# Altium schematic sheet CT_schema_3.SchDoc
size 321 x 189 mm
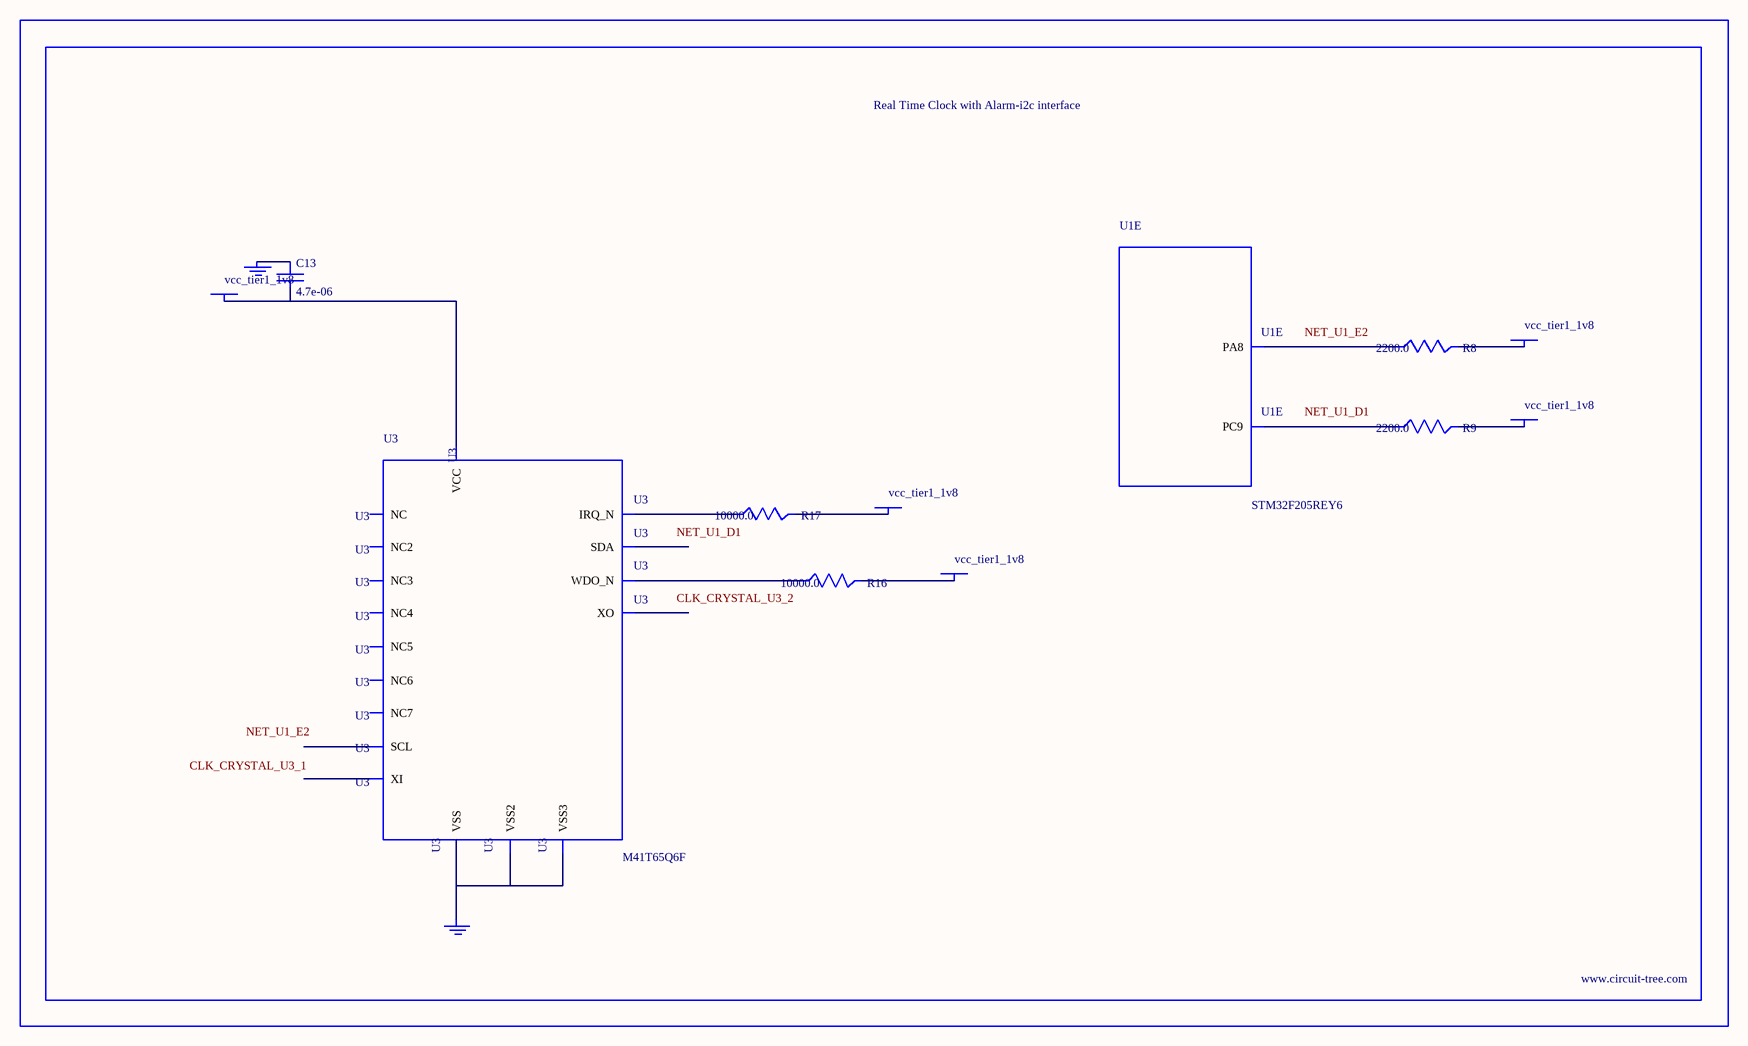
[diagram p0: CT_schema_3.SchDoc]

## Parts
BORDER2  (no value)
C13  4.7e-06  [C0805]
GND_INSTANCE_2_0  (no value)
GND_INSTANCE_2_1  (no value)
POWER_INSTANCE_2_0  vcc_tier1_1v8
POWER_INSTANCE_2_1  vcc_tier1_1v8
POWER_INSTANCE_2_2  vcc_tier1_1v8
POWER_INSTANCE_2_3  vcc_tier1_1v8
POWER_INSTANCE_2_4  vcc_tier1_1v8
R8  2200.0  [R0603]
R9  2200.0  [R0603]
R16  10000.0  [R0603]
R17  10000.0  [R0603]
U1  STM32F205REY6  [WLCSP66]  (part E of 7)
U3  M41T65Q6F  [M41T65_QFN-16]

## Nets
NetC13_1: C13.1 GND_INSTANCE_2_0.0(GND)
NetC13_2: C13.2 POWER_INSTANCE_2_2.0(PWR) U3.14(VCC)
NetGND_INSTANCE_2_1_0: GND_INSTANCE_2_1.0(GND) U3.3(VSS) U3.5(VSS2) U3.17(VSS3)
NetPOWER_INSTANCE_2_0_0: POWER_INSTANCE_2_0.0(PWR) R16.2
NetPOWER_INSTANCE_2_1_0: POWER_INSTANCE_2_1.0(PWR) R17.2
NetPOWER_INSTANCE_2_3_0: POWER_INSTANCE_2_3.0(PWR) R8.2
NetPOWER_INSTANCE_2_4_0: POWER_INSTANCE_2_4.0(PWR) R9.2
NetR8_1: R8.1 U1.E2(PA8)
NetR9_1: R9.1 U1.D1(PC9)
NetR16_1: R16.1 U3.4(WDO_N)
NetR17_1: R17.1 U3.11(IRQ_N)

Not connected (* = marked no-connect by the designer): U3 1(XI) 2(XO) 6(NC) 7(NC2) 8(NC3) 9(SDA) 10(SCL) 12(NC4) 13(NC5) 15(NC6) 16(NC7)

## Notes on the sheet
- Labels drawn without touching a wire or pin: CLK_CRYSTAL_U3_1, CLK_CRYSTAL_U3_2, NET_U1_D1, NET_U1_E2

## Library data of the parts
BORDER2 = BORDER_PAGE2
C13 = C0805C475K4RACTU
GND_INSTANCE_2_0 GND_INSTANCE_2_1 = GND
POWER_INSTANCE_2_0-POWER_INSTANCE_2_4 = PWR
R8 R9 = RC0603JR-072K2L
R16 R17 = RC0603JR-0710KL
